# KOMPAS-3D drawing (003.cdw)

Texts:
  Монтажная схема отопления
  Текст на чертеже
  Размерные надписи
  Шероховатость
  Линия-выноска #1
  Линия-выноска #2
  Линия-выноска #3
  Отклонения формы и база
  Заголовок таблицы
  Ячейка таблицы
  Стрелка вида
  Обозначение изменения
  Фигурная скобка
  Номер узла
  Марка координационной оси
  VRCB
  Выносная надпись
  Обозначение узла
  Марка/позиционное обозначение с линией-выноской
  Марка/позиционное обозначение на линии
  Марка/позиционное обозначение без линии-выноски
  Провести под потолком подвала
  Провести над полом второго этажа
  АМК-3
  Модуль АМК-3
  Радіатор алюмінієвий
  Труба  20
  Труба @2~20
  Труба  25
  Труба @2~25
  Труба  32
  Труба @2~32
  Монтажная схема
  отопления
Dimensions and other numbers on the sheet: 7; 1; 2; 3; 4; 5; 0; 6; 8; 9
